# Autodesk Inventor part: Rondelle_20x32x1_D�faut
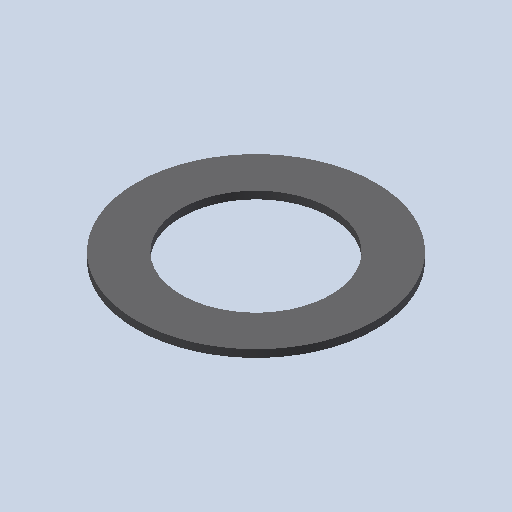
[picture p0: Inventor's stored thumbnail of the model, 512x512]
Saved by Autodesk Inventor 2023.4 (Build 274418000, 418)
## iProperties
Created: 2011-01
Part Number: Rondelle_20x32x1_D�faut
Document SubType Name: Modeling
Designer: eric
Density: 1 g/cm^3
Mass: 0.490088 g
Surface Area: 11.4354 cm^2
Volume: 0.490088 cm^3
Material: Générique
Appearance: Yellow
Author: eric
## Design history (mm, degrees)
feature "Base1"
node "Corps solides"
node "Corps surfaciques"
node "Solide1"
